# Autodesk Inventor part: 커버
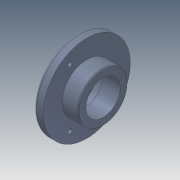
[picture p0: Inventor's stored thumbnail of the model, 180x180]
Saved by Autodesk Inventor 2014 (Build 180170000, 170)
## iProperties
Company: 한국ATC센터
Created: 2014-10
Part Number: 커버
Document SubType Name: Modeling
Designer: 한국ATC센터
Density: 2.71 g/cm^3
Material: 알루미늄-6061
Mass: 189.969 g
Surface Area: 197.235 cm^2
Volume: 70.0991 cm^3
Appearance: 슬레이트 파란색
Author: KYOUNG IL JANG
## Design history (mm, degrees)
sketch "스케치1"
  geometry: L1 (-13.5, 0)-(13.5, 0); L2 (-13.5, 0)-(-13.5, 45.5); L3 (-13.5, 45.5)-(-3.5, 45.5); L4 (-3.5, 45.5)-(-3.5, 26); L5 (-3.5, 26)-(13.5, 26); L6 (13.5, 26)-(13.5, 0); 2 further points
  constraints: 12 end point, 3 parallel, 2 perpendicular, 1 coincident, 1 horizontal, 1 midpoint
  dimensions: "d0" = 27 distance of L1.start L1.end; "d1" = 91 diameter of L3 L1; "d2" = 52 diameter of L5 L1; "d3" = 10 distance of L2.end L3.end
revolve "회전1" sketch "스케치1" stored, may be unused: angle "d4" = 90 deg
hole "구멍1" diameter "d7" = 36; stored, may be unused: countersink angle "d11" = 90 deg, drill point angle "d13" = 118 deg; dims "d5" = 10, "d6" = 10, "d8" = 6, "d9" = 40, "d10" = 8.3, "d12" = 8
sketch "스케치2"
  geometry: 2 further points
  constraints: 1 vertical alignment
  dimensions: "d14" = 35 distance of point (0, 0) point (0, 35)
hole "구멍2" sketch "스케치2" at (0, 35) diameter "d15" = 4.5; stored, may be unused: countersink angle "d19" = 90 deg, drill point angle "d21" = 118 deg; dims "d16" = 6, "d17" = 8, "d18" = 4.4, "d20" = 8
chamfer "모따기1" distance "d25" = 0.8; stored, may be unused: second distance "d26" = 2, angle "d27" = 30 deg
fillet "모깎기1" dims "d28" = 0.1, "d29" = 3
chamfer "모따기2" distance "d30" = 1; stored, may be unused: second distance "d31" = 2, angle "d32" = 30 deg
node "솔리드1"
pattern_circular "원형 패턴1" dims angle "d23" = 360 deg
